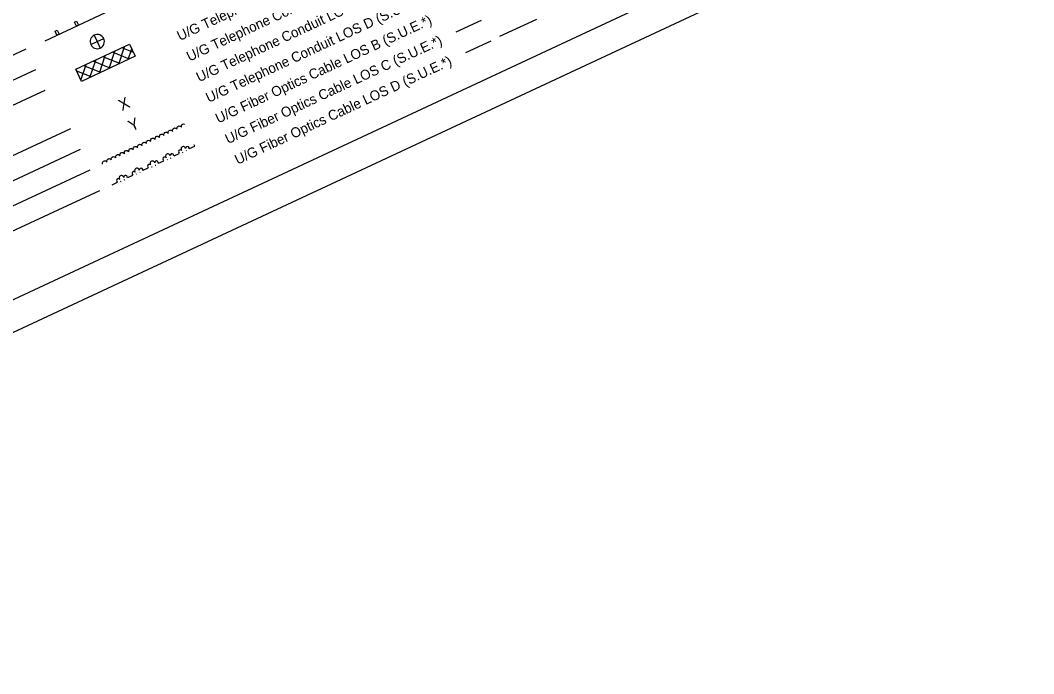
# Model space of a CAD drawing. Extents: x 885291.5 to 885341.7, y 651350.6 to 651393.5.
# Drawn here: x 885319.4 to 885341.67, y 651350.6 to 651364.95 of the extents above; entities that cross this region are included whole.
import ezdxf

# ---------------------------------------------------------------- set-up
doc = ezdxf.new("R2010")
doc.units = 0
doc.layers.add('Sheet Symbology CELL', color=7, linetype='Continuous')
doc.layers.add('Stewart Plot Border Xerox6279 and LJ5000', color=7, linetype='Continuous')

msp = doc.modelspace()

# ---------------------------------------------------------------- linework, layer by layer
at = {"layer": 'Sheet Symbology CELL'}
for p, q in [((885319.943, 651364.499), (885321.756, 651365.344)), ((885329.525, 651364.947), (885328.967, 651364.687)), ((885329.937, 651364.597), (885330.75, 651364.976)), ((885321.022, 651364.622), (885321.088, 651364.481)), ((885320.62, 651363.873), (885321.8, 651364.423)), ((885320.947, 651364.415), (885321.088, 651364.481)), ((885321.088, 651364.481), (885321.23, 651364.547)), ((885321.088, 651364.481), (885321.155, 651364.339)), ((885321.559, 651363.988), (885321.684, 651364.369)), ((885321.8, 651364.423), (885321.924, 651364.158)), ((885329.736, 651364.494), (885329.178, 651364.234)), ((885319.517, 651364.316), (885317.154, 651363.214)), ((885321.924, 651364.158), (885320.743, 651363.608)), ((885321.138, 651363.791), (885321.264, 651364.173)), ((885321.584, 651363.999), (885321.211, 651364.148)), ((885321.348, 651363.89), (885321.474, 651364.271)), ((885321.795, 651364.098), (885321.421, 651364.246)), ((885321.884, 651364.243), (885321.631, 651364.344)), ((885321.769, 651364.086), (885321.847, 651364.323)), ((885320.731, 651363.634), (885320.843, 651363.977)), ((885321.164, 651363.803), (885320.791, 651363.952)), ((885320.928, 651363.694), (885321.054, 651364.075)), ((885321.373, 651363.901), (885321.002, 651364.051)), ((885319.728, 651363.863), (885316.497, 651362.356)), ((885320.743, 651363.608), (885320.62, 651363.873)), ((885320.626, 651363.859), (885320.632, 651363.878)), ((885320.953, 651363.705), (885320.639, 651363.832)), ((885319.94, 651363.41), (885316.708, 651361.903)), ((885322.763, 651362.574), (885322.785, 651362.584)), ((885322.785, 651362.584), (885322.808, 651362.581)), ((885322.808, 651362.581), (885322.827, 651362.572)), ((885322.839, 651362.579), (885322.846, 651362.6)), ((885322.843, 651362.555), (885322.839, 651362.579)), ((885322.846, 651362.6), (885322.859, 651362.619)), ((885322.859, 651362.619), (885322.881, 651362.629)), ((885322.881, 651362.629), (885322.904, 651362.626)), ((885322.904, 651362.626), (885322.924, 651362.617)), ((885322.924, 651362.617), (885322.937, 651362.6)), ((885322.936, 651362.624), (885322.942, 651362.645)), ((885322.939, 651362.599), (885322.936, 651362.624)), ((885322.942, 651362.645), (885322.956, 651362.664)), ((885322.956, 651362.664), (885322.977, 651362.674)), ((885322.977, 651362.674), (885323.001, 651362.671)), ((885323.001, 651362.671), (885323.002, 651362.67)), ((885320.502, 651362.567), (885316.398, 651360.653)), ((885322.282, 651362.35), (885322.303, 651362.36)), ((885322.303, 651362.36), (885322.327, 651362.357)), ((885322.327, 651362.357), (885322.346, 651362.348)), ((885322.358, 651362.355), (885322.365, 651362.376)), ((885322.361, 651362.33), (885322.358, 651362.355)), ((885322.365, 651362.376), (885322.378, 651362.394)), ((885322.378, 651362.394), (885322.399, 651362.405)), ((885322.399, 651362.405), (885322.423, 651362.402)), ((885322.423, 651362.402), (885322.442, 651362.393)), ((885322.442, 651362.393), (885322.456, 651362.376)), ((885322.454, 651362.4), (885322.461, 651362.421)), ((885322.457, 651362.375), (885322.454, 651362.4)), ((885322.461, 651362.421), (885322.474, 651362.439)), ((885322.474, 651362.439), (885322.496, 651362.449)), ((885322.496, 651362.449), (885322.519, 651362.447)), ((885322.519, 651362.447), (885322.538, 651362.438)), ((885322.538, 651362.438), (885322.552, 651362.42)), ((885322.55, 651362.445), (885322.557, 651362.466)), ((885322.554, 651362.42), (885322.55, 651362.445)), ((885322.557, 651362.466), (885322.57, 651362.484)), ((885322.57, 651362.484), (885322.592, 651362.494)), ((885322.592, 651362.494), (885322.615, 651362.491)), ((885322.615, 651362.491), (885322.635, 651362.483)), ((885322.635, 651362.483), (885322.648, 651362.465)), ((885322.647, 651362.489), (885322.653, 651362.511)), ((885322.65, 651362.465), (885322.647, 651362.489)), ((885322.653, 651362.511), (885322.667, 651362.529)), ((885322.667, 651362.529), (885322.688, 651362.539)), ((885322.688, 651362.539), (885322.712, 651362.536)), ((885322.712, 651362.536), (885322.731, 651362.527)), ((885322.731, 651362.527), (885322.745, 651362.51)), ((885322.743, 651362.534), (885322.75, 651362.555)), ((885322.746, 651362.51), (885322.743, 651362.534)), ((885322.75, 651362.555), (885322.763, 651362.574)), ((885322.827, 651362.572), (885322.841, 651362.555)), ((885321.8, 651362.125), (885321.822, 651362.135)), ((885321.822, 651362.135), (885321.845, 651362.132)), ((885321.845, 651362.132), (885321.864, 651362.123)), ((885321.876, 651362.13), (885321.883, 651362.151)), ((885321.883, 651362.151), (885321.896, 651362.17)), ((885321.896, 651362.17), (885321.918, 651362.18)), ((885321.918, 651362.18), (885321.941, 651362.177)), ((885321.941, 651362.177), (885321.961, 651362.168)), ((885321.961, 651362.168), (885321.974, 651362.151)), ((885321.973, 651362.175), (885321.979, 651362.196)), ((885321.976, 651362.15), (885321.973, 651362.175)), ((885321.979, 651362.196), (885321.993, 651362.215)), ((885321.993, 651362.215), (885322.014, 651362.225)), ((885322.014, 651362.225), (885322.038, 651362.222)), ((885322.038, 651362.222), (885322.057, 651362.213)), ((885322.057, 651362.213), (885322.07, 651362.196)), ((885322.069, 651362.22), (885322.076, 651362.241)), ((885322.072, 651362.195), (885322.069, 651362.22)), ((885322.076, 651362.241), (885322.089, 651362.26)), ((885322.089, 651362.26), (885322.111, 651362.27)), ((885322.111, 651362.27), (885322.134, 651362.267)), ((885322.134, 651362.267), (885322.153, 651362.258)), ((885322.153, 651362.258), (885322.167, 651362.241)), ((885322.165, 651362.265), (885322.172, 651362.286)), ((885322.168, 651362.24), (885322.165, 651362.265)), ((885322.172, 651362.286), (885322.185, 651362.305)), ((885322.185, 651362.305), (885322.207, 651362.315)), ((885322.207, 651362.315), (885322.23, 651362.312)), ((885322.23, 651362.312), (885322.25, 651362.303)), ((885322.25, 651362.303), (885322.263, 651362.286)), ((885322.262, 651362.31), (885322.268, 651362.331)), ((885322.265, 651362.285), (885322.262, 651362.31)), ((885322.268, 651362.331), (885322.282, 651362.35)), ((885322.346, 651362.348), (885322.359, 651362.331)), ((885323.116, 651362.13), (885323.229, 651362.183)), ((885320.713, 651362.113), (885316.61, 651360.2)), ((885321.319, 651361.901), (885321.34, 651361.911)), ((885321.34, 651361.911), (885321.364, 651361.908)), ((885321.364, 651361.908), (885321.383, 651361.899)), ((885321.395, 651361.906), (885321.402, 651361.927)), ((885321.402, 651361.927), (885321.415, 651361.945)), ((885321.415, 651361.945), (885321.436, 651361.955)), ((885321.436, 651361.955), (885321.46, 651361.953)), ((885321.46, 651361.953), (885321.479, 651361.944)), ((885321.479, 651361.944), (885321.493, 651361.927)), ((885321.491, 651361.951), (885321.498, 651361.972)), ((885321.494, 651361.926), (885321.491, 651361.951)), ((885321.498, 651361.972), (885321.511, 651361.99)), ((885321.511, 651361.99), (885321.533, 651362)), ((885321.533, 651362), (885321.556, 651361.998)), ((885321.556, 651361.998), (885321.576, 651361.989)), ((885321.576, 651361.989), (885321.589, 651361.971)), ((885321.587, 651361.996), (885321.594, 651362.017)), ((885321.591, 651361.971), (885321.587, 651361.996)), ((885321.594, 651362.017), (885321.608, 651362.035)), ((885321.608, 651362.035), (885321.629, 651362.045)), ((885321.629, 651362.045), (885321.652, 651362.042)), ((885321.652, 651362.042), (885321.672, 651362.033)), ((885321.672, 651362.033), (885321.685, 651362.016)), ((885321.684, 651362.04), (885321.69, 651362.062)), ((885321.687, 651362.016), (885321.684, 651362.04)), ((885321.69, 651362.062), (885321.704, 651362.08)), ((885321.704, 651362.08), (885321.725, 651362.09)), ((885321.725, 651362.09), (885321.749, 651362.087)), ((885321.749, 651362.087), (885321.768, 651362.078)), ((885321.768, 651362.078), (885321.782, 651362.061)), ((885321.78, 651362.085), (885321.787, 651362.106)), ((885321.783, 651362.061), (885321.78, 651362.085)), ((885321.787, 651362.106), (885321.8, 651362.125)), ((885321.864, 651362.123), (885321.878, 651362.106)), ((885321.88, 651362.106), (885321.876, 651362.13)), ((885322.701, 651361.923), (885322.712, 651361.928)), ((885322.776, 651361.972), (885322.89, 651362.025)), ((885322.962, 651362.045), (885322.973, 651362.05)), ((885323.041, 651362.082), (885323.052, 651362.087)), ((885321.202, 651361.816), (885321.209, 651361.837)), ((885321.205, 651361.791), (885321.202, 651361.816)), ((885321.209, 651361.837), (885321.222, 651361.856)), ((885321.222, 651361.856), (885321.244, 651361.866)), ((885321.244, 651361.866), (885321.267, 651361.863)), ((885321.267, 651361.863), (885321.287, 651361.854)), ((885321.287, 651361.854), (885321.3, 651361.837)), ((885321.299, 651361.861), (885321.305, 651361.882)), ((885321.302, 651361.836), (885321.299, 651361.861)), ((885321.305, 651361.882), (885321.319, 651361.901)), ((885321.383, 651361.899), (885321.396, 651361.882)), ((885321.398, 651361.881), (885321.395, 651361.906)), ((885322.097, 651361.655), (885322.21, 651361.708)), ((885322.282, 651361.728), (885322.293, 651361.733)), ((885322.361, 651361.765), (885322.373, 651361.77)), ((885322.436, 651361.814), (885322.55, 651361.866)), ((885322.622, 651361.886), (885322.633, 651361.891)), ((885320.925, 651361.66), (885316.106, 651359.413)), ((885321.757, 651361.497), (885321.87, 651361.549)), ((885321.942, 651361.569), (885321.953, 651361.575)), ((885322.021, 651361.606), (885322.033, 651361.611)), ((885321.417, 651361.338), (885321.53, 651361.391)), ((885321.602, 651361.411), (885321.614, 651361.416)), ((885321.682, 651361.448), (885321.693, 651361.453)), ((885321.136, 651361.207), (885317.032, 651359.293))]:
    msp.add_line(p, q, dxfattribs=at)
for points in [[(885329.923, 651392.736), (885295.937, 651376.888), (885307.02, 651353.12), (885341.006, 651368.969)], [(885320.591, 651364.911), (885320.636, 651364.932), (885320.679, 651364.842), (885320.633, 651364.821)], [(885320.16, 651364.71), (885320.206, 651364.732), (885320.248, 651364.641), (885320.203, 651364.62)]]:
    msp.add_lwpolyline(points, close=True, dxfattribs=at)
for centre, radius, start, end in [((885321.089, 651364.481), 0.156, 114.9944, 204.9989), ((885321.089, 651364.481), 0.156, 24.9944, 114.9989), ((885321.089, 651364.481), 0.156, 204.9944, 294.9989), ((885321.089, 651364.481), 0.156, 294.9944, 24.9989), ((885322.98, 651362.123), 0.0515, 10.9638, 219.0362), ((885323.07, 651362.137), 0.0395, 345.7685, 186.565), ((885323.251, 651362.222), 0.0395, 181.251, 228.749), ((885322.572, 651361.905), 0.0395, 43.4349, 244.2315), ((885322.64, 651361.964), 0.0515, 10.9638, 219.0362), ((885322.73, 651361.979), 0.0395, 345.7685, 186.565), ((885322.912, 651362.063), 0.0395, 43.4349, 244.2315), ((885321.961, 651361.647), 0.0515, 10.9638, 219.0362), ((885322.051, 651361.662), 0.0395, 345.7685, 186.565), ((885322.232, 651361.746), 0.0395, 43.4349, 244.2315), ((885322.301, 651361.806), 0.0515, 10.9638, 219.0362), ((885322.39, 651361.82), 0.0395, 345.7685, 186.565), ((885321.552, 651361.429), 0.0395, 43.4349, 244.2315), ((885321.621, 651361.489), 0.0515, 10.9638, 219.0362), ((885321.711, 651361.503), 0.0395, 345.7685, 186.565), ((885321.892, 651361.588), 0.0395, 43.4349, 244.2315)]:
    msp.add_arc(centre, radius, start, end, dxfattribs=at)
at = {"layer": 'Stewart Plot Border Xerox6279 and LJ5000'}
msp.add_lwpolyline([(885303.148, 651350.597), (885341.666, 651368.559), (885330.044, 651393.482), (885291.526, 651375.521)], close=True, dxfattribs=at)

# ---------------------------------------------------------------- texts
at = {"layer": 'Sheet Symbology CELL'}
for s, height, p in [('U/G Telephone Cable LOS D (S.U.E.*)', 0.21875, (885322.904, 651364.493)), ('U/G Telephone Conduit LOS B (S.U.E.*)', 0.21875, (885323.115, 651364.04)), ('U/G Telephone Conduit LOS C (S.U.E.*)', 0.21875, (885323.327, 651363.587)), ('U/G Telephone Conduit LOS D (S.U.E.*)', 0.21875, (885323.538, 651363.134)), ('U/G Fiber Optics Cable LOS B (S.U.E.*)', 0.21875, (885323.749, 651362.681)), ('U/G Fiber Optics Cable LOS C (S.U.E.*)', 0.21875, (885323.961, 651362.227)), ('U/G Fiber Optics Cable LOS D (S.U.E.*)', 0.21875, (885324.172, 651361.774)), ('X', 0.25, (885321.629, 651362.954)), ('Y', 0.25, (885321.84, 651362.501))]:
    msp.add_text(s, height=height, rotation=25, dxfattribs=at).set_placement(p)

doc.saveas('drawing.dxf')
